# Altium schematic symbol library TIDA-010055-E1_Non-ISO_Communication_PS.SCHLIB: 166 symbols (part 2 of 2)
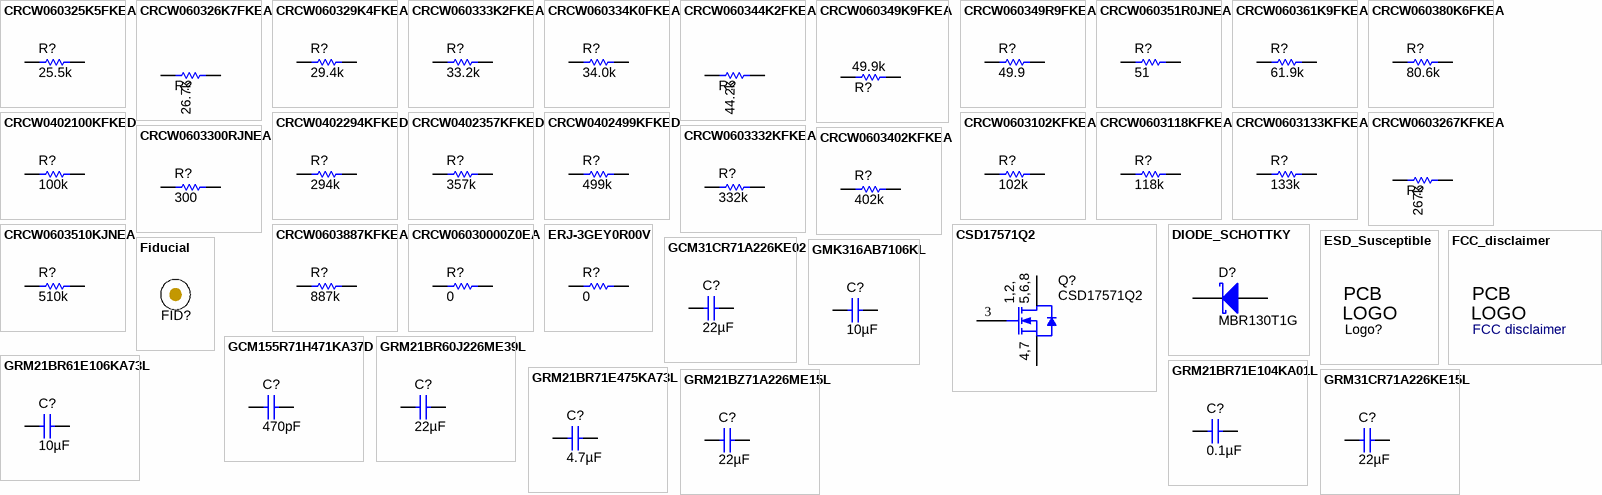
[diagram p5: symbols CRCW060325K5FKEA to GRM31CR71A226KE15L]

## CRCW0402499KFKED
designator R?  ValueDisplayed: 499k  (hidden comment: CRCW0402499KFKED)
RES, 499 k, 1%, 0.063 W, 0402; Manufacturer: Vishay-Dale; CompType: Resistor; Value: 499k; Res_ohm: 499000; Tolerance_%: 1; Power_W: 0.063; Value2: 0.063W; VDC_V: 50; TempCo: 100 ppm/C; EIA_Code: E96; U/M: EA; AEC Category: Q200
signal-integrity model Resistor
simulation model Resistor
footprint 0402
footprint 0402M
footprint 0402L
footprint 0402S
pins: 1, 2

## CRCW0603102KFKEA
designator R?  ValueDisplayed: 102k  (hidden comment: CRCW0603102KFKEA)
RES, 102 k, 1%, 0.1 W, 0603; Manufacturer: Vishay-Dale; CompType: Resistor; Value: 102k; Res_ohm: 102000; Tolerance_%: 1; Power_W: 0.1; Value2: 0.1W; VDC_V: 75; TempCo: 100 ppm/C; SizeArea_mm2: 1.28; SizeX_mm: 1.6; SizeY_mm: 0.8; EIA_Code: E96; U/M: EA; AEC Category: Q200; Green_Lifecycle: Active; Green_REACh: Passed
signal-integrity model Resistor
simulation model Resistor
footprint 0603
footprint 0603M
footprint 0603L
footprint 0603_HV
footprint 0603S
pins: 1, 2

## CRCW0603118KFKEA
designator R?  ValueDisplayed: 118k  (hidden comment: CRCW0603118KFKEA)
RES, 118 k, 1%, 0.1 W, 0603; Manufacturer: Vishay-Dale; CompType: Resistor; Value: 118k; Res_ohm: 118000; Tolerance_%: 1; Power_W: 0.1; Value2: 0.1W; VDC_V: 75; TempCo: 100 ppm/C; EIA_Code: E96; U/M: EA; AEC Category: Q200
signal-integrity model Resistor
simulation model Resistor
footprint 0603
footprint 0603M
footprint 0603L
footprint 0603_HV
footprint 0603S
pins: 1, 2

## CRCW0603133KFKEA
designator R?  ValueDisplayed: 133k  (hidden comment: CRCW0603133KFKEA)
RES, 133 k, 1%, 0.1 W, 0603; Manufacturer: Vishay-Dale; CompType: Resistor; Value: 133k; Res_ohm: 133000; Tolerance_%: 1; Power_W: 0.1; Value2: 0.1W; VDC_V: 75; TempCo: 100 ppm/C; SizeArea_mm2: 1.28; SizeX_mm: 1.6; SizeY_mm: 0.8; EIA_Code: E96; U/M: EA; AEC Category: Q200; Green_Lifecycle: Active; Green_REACh: Passed
signal-integrity model Resistor
simulation model Resistor
footprint 0603
footprint 0603M
footprint 0603L
footprint 0603_HV
footprint 0603S
pins: 1, 2

## CRCW0603267KFKEA
designator R?  ValueDisplayed: 267k  (hidden comment: CRCW0603267KFKEA)
RES, 267 k, 1%, 0.1 W, 0603; Manufacturer: Vishay-Dale; CompType: Resistor; Value: 267k; Res_ohm: 267000; Tolerance_%: 1; Power_W: 0.1; Value2: 0.1W; VDC_V: 75; TempCo: 100 ppm/C; SizeArea_mm2: 1.28; SizeX_mm: 1.6; SizeY_mm: 0.8; EIA_Code: E96; U/M: EA; AEC Category: Q200
signal-integrity model Resistor
simulation model Resistor
footprint 0603
footprint 0603M
footprint 0603L
footprint 0603_HV
footprint 0603S
pins: 1, 2

## CRCW0603300RJNEA
designator R?  ValueDisplayed: 300  (hidden comment: CRCW0603300RJNEA)
RES, 300, 5%, 0.1 W, 0603; Manufacturer: Vishay-Dale; CompType: Resistor; Value: 300; Value_Code: 300R; Tolerance_%: 5; Power_W: 0.1; Value2: 0.1W; VDC_V: 75; TempCo: 200 ppm/C; SizeArea_mm2: 1.28; SizeX_mm: 1.6; SizeY_mm: 0.8; SizeZ_mm: 1; EIA_Code: E24; U/M: EA; AEC Category: Q200
signal-integrity model Resistor
simulation model Resistor
footprint 0603
footprint 0603M
footprint 0603L
footprint 0603_HV
footprint 0603S
pins: 1, 2

## CRCW0603332KFKEA
designator R?  ValueDisplayed: 332k  (hidden comment: CRCW0603332KFKEA)
RES, 332 k, 1%, 0.1 W, 0603; Manufacturer: Vishay-Dale; CompType: Resistor; Value: 332k; Res_ohm: 332000; Tolerance_%: 1; Power_W: 0.1; Value2: 0.1W; VDC_V: 75; TempCo: 100 ppm/C; SizeArea_mm2: 1.28; SizeX_mm: 1.6; SizeY_mm: 0.8; EIA_Code: E96; U/M: EA; AEC Category: Q200; Green_Lifecycle: Active; Green_REACh: Passed
signal-integrity model Resistor
simulation model Resistor
footprint 0603
footprint 0603M
footprint 0603L
footprint 0603_HV
footprint 0603S
pins: 1, 2

## CRCW0603402KFKEA
designator R?  ValueDisplayed: 402k  (hidden comment: CRCW0603402KFKEA)
RES, 402 k, 1%, 0.1 W, 0603; Manufacturer: Vishay-Dale; CompType: Resistor; Value: 402k; Res_ohm: 402000; Tolerance_%: 1; Power_W: 0.1; Value2: 0.1W; VDC_V: 75; TempCo: 100 ppm/C; SizeArea_mm2: 1.28; SizeX_mm: 1.6; SizeY_mm: 0.8; EIA_Code: E96; U/M: EA; AEC Category: Q200; Green_Lifecycle: Active; Green_REACh: Passed
signal-integrity model Resistor
simulation model Resistor
footprint 0603
footprint 0603M
footprint 0603L
footprint 0603_HV
footprint 0603S
pins: 1, 2

## CRCW0603510KJNEA
designator R?  ValueDisplayed: 510k  (hidden comment: CRCW0603510KJNEA)
RES, 510 k, 5%, 0.1 W, 0603; Manufacturer: Vishay-Dale; CompType: Resistor; Value: 510k; Res_ohm: 510000; Tolerance_%: 5; Power_W: 0.1; Value2: 0.1W; VDC_V: 75; TempCo: 200 ppm/C; EIA_Code: E24; U/M: EA; AEC Category: Q200
signal-integrity model Resistor
simulation model Resistor
footprint 0603
footprint 0603M
footprint 0603L
footprint 0603_HV
footprint 0603S
pins: 1, 2

## CRCW0603887KFKEA
designator R?  ValueDisplayed: 887k  (hidden comment: CRCW0603887KFKEA)
RES, 887 k, 1%, 0.1 W, 0603; Manufacturer: Vishay-Dale; CompType: Resistor; Value: 887k; Res_ohm: 887000; Tolerance_%: 1; Power_W: 0.1; Value2: 0.1W; VDC_V: 75; TempCo: 100 ppm/C; SizeArea_mm2: 1.28; SizeX_mm: 1.6; SizeY_mm: 0.8; EIA_Code: E96; U/M: EA; AEC Category: Q200; Green_Lifecycle: Active; Green_REACh: Passed
signal-integrity model Resistor
simulation model Resistor
footprint 0603
footprint 0603M
footprint 0603L
footprint 0603_HV
footprint 0603S
pins: 1, 2

## CRCW06030000Z0EA
designator R?  ValueDisplayed: 0  (hidden comment: CRCW06030000Z0EA)
RES, 0, 5%, 0.1 W, 0603; Manufacturer: Vishay-Dale; CompType: Resistor; Value: 0; Value_Code: 0000; Tolerance_%: 5; Power_W: 0.1; Value2: 0.1W; VDC_V: 75; TempCo: 200 ppm/C; EIA_Code: E24; U/M: EA; AEC Category: Q200
signal-integrity model Resistor
simulation model Resistor
footprint 0603
footprint 0603M
footprint 0603L
footprint 0603_HV
footprint 0603S
pins: 1, 2

## CSD17571Q2
designator Q?
MOSFET, N-CH, 30 V, 22 A, DQK0006C (WSON-6); Manufacturer: Texas Instruments; Alternate Manufacturer: None; U/M: EA; ChType: N; Value: 30V; VdsMax_V: 30; Value1: 0.029 ohm; Rdson45_ohm: 0.029; Value2: 2.4 nC; QgTyp_nC: 2.4; Vgs_V: 20; IdsMax_A: 22; SizeAreaWB_mm2: 9; SizeArea_mm2: 4; SizeX_mm: 2; SizeZ_mm: 0.8; AEC Category: Q101
footprint DQK0006C
pins: 1 D, 2 D, 3 G, 4 S, 5 D, 6 D, 7 S, 8 D

## DIODE_SCHOTTKY
designator D?, comment MBR130T1G
Diode, Schottky, 30 V, 1 A, SOD-123; Manufacturer: ON Semiconductor; Io_A: 1A; Green_Lifecycle: Active; SizeAreaWB_mm2: 13.095; Vr_V: 30V; Green_REACh: Passed; TJmax_C: 125°C; U/M: EA; Value: 30V; SizeZ_mm: 1.35; SizeX_mm: 3.85; SizeY_mm: 1.7; Vf_V: 4.7dV; Value2: 0.47V; SizeArea_mm2: 6.545; AEC Category: Q101; RJC_CperW: 108
footprint SOD-123 (On Semi recommended land pattern)
pins: 1 K, 2 A

## ERJ-3GEY0R00V
designator R?  ValueDisplayed: 0  (hidden comment: ERJ-3GEY0R00V)
RES, 0, 5%, 0.1 W, 0603; Manufacturer: Panasonic; CompType: Resistor; Value: 0; Value_Code: 0000; Tolerance_%: 5; Power_W: 0.1; Value2: 0.1W; VDC_V: 50; TempCo: 600 ppm/C; SizeArea_mm2: 1.28; SizeX_mm: 1.6; SizeY_mm: 0.8; SizeZ_mm: 1; EIA_Code: E24; U/M: EA; AEC Category: Q200; Green_Lifecycle: Active; Green_REACh: Passed
signal-integrity model Resistor
simulation model Resistor
footprint 0603
footprint 0603M
footprint 0603L
footprint 0603_HV
footprint 0603S
pins: 1, 2

## ESD_Susceptible
designator Logo?, comment ESD Susceptible  (value not drawn)  (no BOM)
ESD Susceptible Symbol; SymbolCreator: a0412235
footprint ESD_Overlay_Large
footprint ESD_Overlay_Medium
footprint ESD_Overlay_Small

## FCC_disclaimer
designator Logo?, comment FCC disclaimer  (no BOM)
FCC_disclaimer; SymbolCreator: codlsc
footprint FCC_disclaimer
footprint FCC_disclaimer_stacked

## Fiducial
designator FID?  (value not drawn)
Fiducial mark.  There is nothing to buy or mount.; SymbolCreator: codlsc
footprint Fiducial10-30
footprint Fiducial10-20
footprint Fiducial15-30
footprint Fiducial20-40
footprint Fiducial6.4-20

## GCM31CR71A226KE02
designator C?  ValueDisplayed: 22µF  (hidden comment: GCM31CR71A226KE02)
CAP, CERM, 22 µF, 10 V, +/- 10%, X7R, AEC-Q200 Grade 1, 1206_190; Manufacturer: MuRata; Polarized: N; CompType: Capacitor; Value: 22uF; U/M: EA; Cap_F: 0.000022; Tolerance_%: 10; Value1: Unknown; Value2: 10V; TaMin_C: -55; TaMax_C: 125; Cap_Case: 1206; AEC Category: Q200; AEC Qualified: Y; AEC Grade: 1
signal-integrity model Cap
simulation model Cap
footprint 1206_190
footprint 1206_190M
footprint 1206_190L
pins: 1, 2

## GCM155R71H471KA37D
designator C?  ValueDisplayed: 470pF  (hidden comment: GCM155R71H471KA37D)
CAP, CERM, 470 pF, 50 V, +/- 10%, X7R, AEC-Q200 Grade 1, 0402; Manufacturer: MuRata; Polarized: N; CompType: Capacitor; Value: 470pF; U/M: EA; Cap_F: 0.00000000047; Tolerance_%: 10; Value1: Unknown; VDC_V: 50; Value2: 50V; TaMin_C: -55; TaMax_C: 125; Cap_Case: 0402; AEC Category: Q200; AEC Qualified: Y; AEC Grade: 1
signal-integrity model Cap
simulation model Cap
footprint 0402
footprint 0402M
footprint 0402L
footprint 0402S
pins: 1, 2

## GMK316AB7106KL
designator C?  ValueDisplayed: 10µF  (hidden comment: GMK316AB7106KL)
CAP, CERM, 10 µF, 35 V, +/- 10%, X7R, 1206; Manufacturer: Taiyo Yuden; Polarized: N; CompType: Capacitor; Value: 10uF; U/M: EA; Cap_F: 0.00001; Tolerance_%: 10; Value1: Unknown; VDC_V: 35; Value2: 35V; TaMin_C: -55; TaMax_C: 125; Cap_Case: 1206; AEC Category: Q200
signal-integrity model Cap
simulation model Cap
footprint 1206
footprint 1206M
footprint 1206L
pins: 1, 2

## GRM21BR60J226ME39L
designator C?  ValueDisplayed: 22µF  (hidden comment: GRM21BR60J226ME39L)
CAP, CERM, 22 µF, 6.3 V, +/- 20%, X5R, 0805; Manufacturer: MuRata; Polarized: N; CompType: Capacitor; Value: 22uF; U/M: EA; Cap_F: 0.000022; Tolerance_%: 20; ESR_ohm: 0.009; Value1: 0.009 ohm; VDC_V: 6.3; Value2: 6.3V; IRMS_A: 3.5; TaMin_C: -55; TaMax_C: 85; Cap_Case: 0805; AEC Category: Q200
signal-integrity model Cap
simulation model Cap
footprint 0805_HV
footprint 0805_HV1
footprint 0805
footprint 0805M
footprint 0805L
pins: 1, 2

## GRM21BR61E106KA73L
designator C?, comment ValueDisplayed: 10µF  (hidden comment: C2012X5R1E106K085AC)
CAP, CERM, 10 µF, 25 V, +/- 10%, X5R, 0805; Manufacturer: TDK Corporation; Polarized: N; CompType: Capacitor; Value: 10uF; U/M: EA; Cap_F: 0.00001; Tolerance_%: 10; Value1: Unknown; VDC_V: 25; Value2: 25V; TaMin_C: -55; TaMax_C: 85; Cap_Case: 0805; AEC Category: Q200
signal-integrity model Cap
simulation model Cap
footprint 0805_HV
footprint 0805_HV1
footprint 0805
footprint 0805M
footprint 0805L
pins: 1, 2

## GRM21BR71E104KA01L
designator C?  ValueDisplayed: 0.1µF  (hidden comment: GRM21BR71E104KA01L)
CAP, CERM, 0.1 µF, 25 V, +/- 10%, X7R, 0805; Manufacturer: MuRata; Polarized: N; CompType: Capacitor; Value: 0.1uF; U/M: EA; Cap_F: 0.0000001; Tolerance_%: 10; Value1: Unknown; VDC_V: 25; Value2: 25V; TaMin_C: -55; TaMax_C: 125; Cap_Case: 0805; AEC Category: Q200
signal-integrity model Cap
simulation model Cap
footprint 0805_HV
footprint 0805_HV1
footprint 0805
footprint 0805M
footprint 0805L
pins: 1, 2

## GRM21BR71E475KA73L
designator C?  ValueDisplayed: 4.7µF  (hidden comment: GRM21BR71E475KA73L)
CAP, CERM, 4.7 µF, 25 V,+/- 10%, X7R, 0805; Manufacturer: MuRata; Polarized: N; CompType: Capacitor; Value: 4.7uF; U/M: EA; Cap_F: 0.0000047; Tolerance_%: 10; VDC_V: 25; Value2: 25V; TaMin_C: -55; TaMax_C: 125; Cap_Case: 0805; SizeArea_mm2: 2.5; SizeAreaWB_mm2: 6.75; SizeX_mm: 2; SizeY_mm: 1.25; SizeZ_mm: 1.45; AEC Category: Q200
signal-integrity model Cap
simulation model Cap
footprint 0805_HV
footprint 0805_HV1
footprint 0805
footprint 0805M
footprint 0805L
pins: 1, 2

## GRM21BZ71A226ME15L
designator C?  ValueDisplayed: 22µF  (hidden comment: GRM21BZ71A226ME15L)
CAP, CERM, 22 µF, 10 V, +/- 20%, X7R, 0805; Manufacturer: MuRata; Polarized: N; CompType: Capacitor; Value: 22uF; U/M: EA; Cap_F: 0.000022; Tolerance_%: 20; Value1: Unknown; VDC_V: 10; Value2: 10V; TaMin_C: -55; TaMax_C: 125; Cap_Case: 0805; AEC Category: Q200
signal-integrity model Cap
simulation model Cap
footprint 0805_HV
footprint 0805_HV1
footprint 0805
footprint 0805M
footprint 0805L
pins: 1, 2

## GRM31CR71A226KE15L
designator C?  ValueDisplayed: 22µF  (hidden comment: GRM31CR71A226KE15L)
CAP, CERM, 22 µF, 10 V, +/- 10%, X7R, 1206; Manufacturer: MuRata; Polarized: N; CompType: Capacitor; Value: 22uF; U/M: EA; Cap_F: 0.000022; Tolerance_%: 10; Value1: Unknown; Value2: 10V; TaMin_C: -55; TaMax_C: 125; Cap_Case: 1206; AEC Category: Q200
signal-integrity model Cap
simulation model Cap
footprint 1206 (1206 from SM-752 data)
footprint 1206M
footprint 1206L
pins: 1, 2

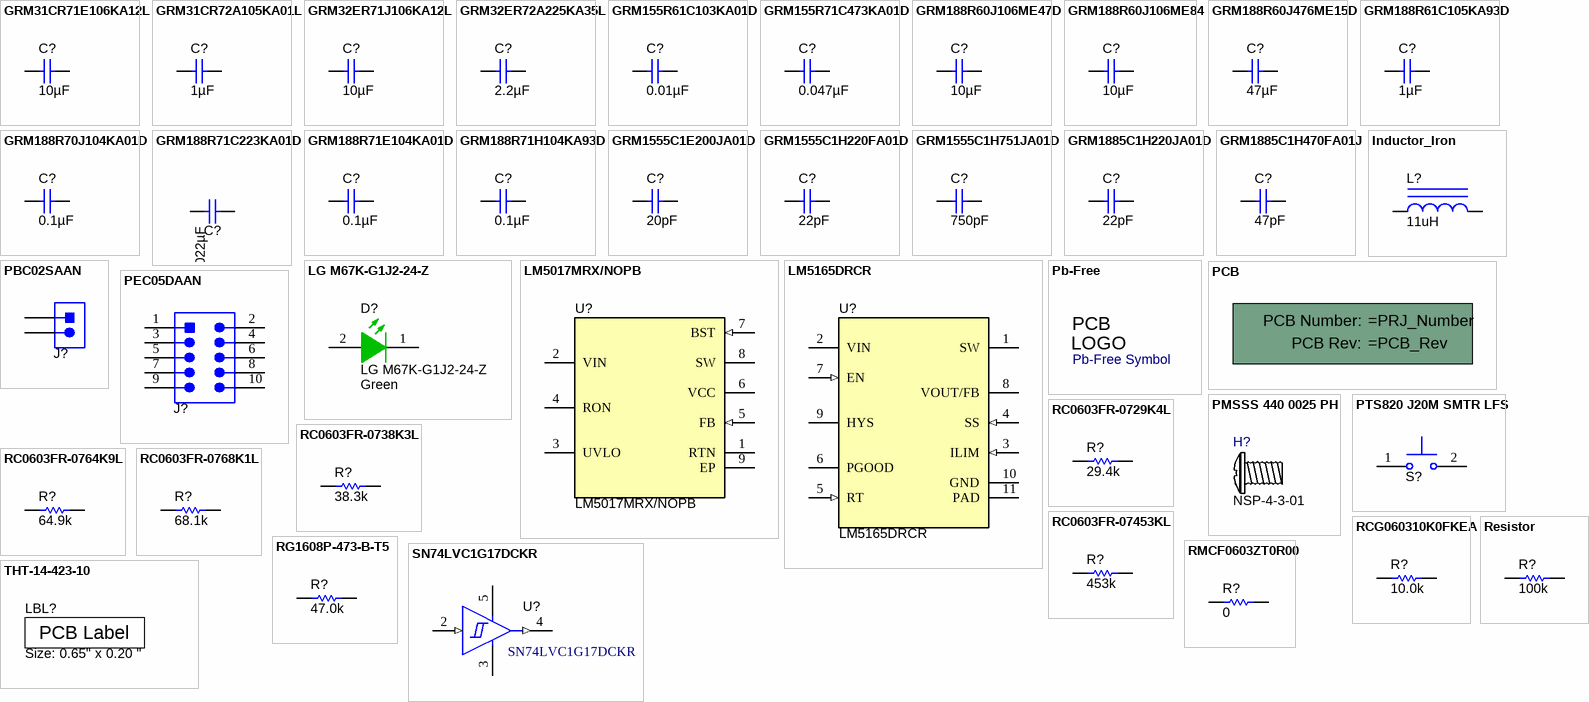
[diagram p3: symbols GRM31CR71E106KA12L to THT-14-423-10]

## GRM31CR71E106KA12L
designator C?  ValueDisplayed: 10µF  (hidden comment: GRM31CR71E106KA12L)
CAP, CERM, 10 µF, 25 V, +/- 10%, X7R, 1206; Manufacturer: MuRata; Polarized: N; CompType: Capacitor; Value: 10uF; U/M: EA; Cap_F: 0.00001; Tolerance_%: 10; Value1: Unknown; VDC_V: 25; Value2: 25V; TaMin_C: -55; TaMax_C: 125; Cap_Case: 2220; AEC Category: Q200
signal-integrity model Cap
simulation model Cap
footprint 1206 (1206 from SM-752 data)
footprint 1206M
footprint 1206L
pins: 1, 2

## GRM31CR72A105KA01L
designator C?  ValueDisplayed: 1µF  (hidden comment: GRM31CR72A105KA01L)
CAP, CERM, 1 µF, 100 V, +/- 10%, X7R, 1206; Manufacturer: MuRata; Polarized: N; CompType: Capacitor; Value: 1uF; U/M: EA; Cap_F: 0.000001; Tolerance_%: 10; Value1: Unknown; VDC_V: 100; Value2: 100V; TaMin_C: -55; TaMax_C: 125; Cap_Case: 2220; AEC Category: Q200
signal-integrity model Cap
simulation model Cap
footprint 1206 (1206 from SM-752 data)
footprint 1206M
footprint 1206L
pins: 1, 2

## GRM32ER71J106KA12L
designator C?  ValueDisplayed: 10µF  (hidden comment: GRM32ER71J106KA12L)
CAP, CERM, 10 µF, 63 V, +/- 10%, X7R, 1210; Manufacturer: MuRata; Polarized: N; CompType: Capacitor; Value: 10uF; U/M: EA; Cap_F: 0.00001; Tolerance_%: 10; Value1: Unknown; VDC_V: 63; Value2: 63V; TaMin_C: -55; TaMax_C: 125; Cap_Case: 1210; SizeArea_mm2: 8; SizeAreaWB_mm2: 14.7; SizeX_mm: 3.2; SizeY_mm: 2.5; SizeZ_mm: 2.7; AEC Category: Q200
signal-integrity model Cap
simulation model Cap
footprint 1210_270
footprint 1210_270M
footprint 1210_270L
pins: 1, 2

## GRM32ER72A225KA35L
designator C?  ValueDisplayed: 2.2µF  (hidden comment: GRM32ER72A225KA35L)
CAP, CERM, 2.2 µF, 100 V, +/- 10%, X7R, 1210; Manufacturer: MuRata; Polarized: N; CompType: Capacitor; Value: 2.2uF; U/M: EA; Cap_F: 0.0000022; Tolerance_%: 10; ESR_ohm: 0.007; Value1: 0.007 ohm; VDC_V: 100; Value2: 100V; IRMS_A: 4.4; TaMin_C: -55; TaMax_C: 125; Cap_Case: 1210; SizeArea_mm2: 8; SizeAreaWB_mm2: 14.7; SizeX_mm: 3.2; SizeY_mm: 2.5; SizeZ_mm: 2.7; AEC Category: Q200
signal-integrity model Cap
simulation model Cap
footprint 1210_270
footprint 1210_270M
footprint 1210_270L
pins: 1, 2

## GRM155R61C103KA01D
designator C?  ValueDisplayed: 0.01µF  (hidden comment: GRM155R61C103KA01D)
CAP, CERM, 0.01 µF, 16 V, +/- 10%, X5R, 0402; Manufacturer: MuRata; Polarized: N; CompType: Capacitor; Value: 0.01uF; U/M: EA; Cap_F: 0.00000001; Tolerance_%: 10; Value1: Unknown; VDC_V: 16; Value2: 16V; TaMin_C: -55; TaMax_C: 85; Cap_Case: 0402; SizeArea_mm2: 0.5; SizeAreaWB_mm2: 3; SizeX_mm: 1; SizeZ_mm: 0.6; AEC Category: Q200
signal-integrity model Cap
simulation model Cap
footprint 0402
footprint 0402M
footprint 0402L
footprint 0402S
pins: 1, 2

## GRM155R71C473KA01D
designator C?  ValueDisplayed: 0.047µF  (hidden comment: GRM155R71C473KA01D)
CAP, CERM, 0.047 µF, 16 V, +/- 10%, X7R, 0402; Manufacturer: MuRata; Polarized: N; CompType: Capacitor; Value: 0.047uF; U/M: EA; Cap_F: 0.000000047; Tolerance_%: 10; Value1: Unknown; VDC_V: 16; Value2: 16V; TaMin_C: -55; TaMax_C: 125; Cap_Case: 0402; AEC Category: Q200
signal-integrity model Cap
simulation model Cap
footprint 0402
footprint 0402M
footprint 0402L
footprint 0402S
pins: 1, 2

## GRM188R60J106ME47D
designator C?  ValueDisplayed: 10µF  (hidden comment: GRM188R60J106ME47D)
CAP, CERM, 10 µF, 6.3 V, +/- 20%, X5R, 0603; Manufacturer: MuRata; Polarized: N; CompType: Capacitor; Value: 10uF; U/M: EA; Cap_F: 0.00001; Tolerance_%: 20; ESR_ohm: 0.009; Value1: 0.009 ohm; VDC_V: 6.3; Value2: 6.3V; IRMS_A: 2.74; TaMin_C: -55; TaMax_C: 125; Cap_Case: 0603; SizeArea_mm2: 1.28; SizeAreaWB_mm2: 4.68; SizeX_mm: 1.6; SizeY_mm: 0.8; SizeZ_mm: 1; AEC Category: Q200
signal-integrity model Cap
simulation model Cap
footprint 0603
footprint 0603M
footprint 0603L
footprint 0603_HV
footprint 0603S
pins: 1, 2

## GRM188R60J106ME84
designator C?  ValueDisplayed: 10µF  (hidden comment: GRM188R60J106ME84)
CAP, CERM, 10 µF, 6.3 V, +/- 20%, X5R, 0603; Manufacturer: MuRata; Polarized: N; CompType: Capacitor; Value: 10uF; U/M: EA; Cap_F: 0.00001; Tolerance_%: 20; Value1: Unknown; VDC_V: 6.3; Value2: 6.3V; TaMin_C: -55; TaMax_C: 85; Cap_Case: 0603; AEC Category: Q200
signal-integrity model Cap
simulation model Cap
footprint 0603
footprint 0603M
footprint 0603L
footprint 0603_HV
footprint 0603S
pins: 1, 2

## GRM188R60J476ME15D
designator C?  ValueDisplayed: 47µF  (hidden comment: GRM188R60J476ME15D)
CAP, CERM, 47 µF, 6.3 V,+/- 20%, X5R, 0603; Manufacturer: MuRata; Polarized: N; CompType: Capacitor; Value: 47uF; U/M: EA; Cap_F: 0.000047; Tolerance_%: 20; VDC_V: 6.3; Value2: 6.3V; TaMin_C: -55; TaMax_C: 85; Cap_Case: 0603; SizeArea_mm2: 1.28; SizeAreaWB_mm2: 4.68; SizeX_mm: 1.6; SizeY_mm: 0.8; SizeZ_mm: 1; AEC Category: Q200; Green_Lifecycle: Active; Green_REACh: Passed
signal-integrity model Cap
simulation model Cap
footprint 0603
footprint 0603M
footprint 0603L
footprint 0603_HV
footprint 0603S
pins: 1, 2

## GRM188R61C105KA93D
designator C?  ValueDisplayed: 1µF  (hidden comment: GRM188R61C105KA93D)
CAP, CERM, 1 µF, 16 V, +/- 10%, X5R, 0603; Manufacturer: MuRata; Polarized: N; CompType: Capacitor; Value: 1uF; U/M: EA; Cap_F: 0.000001; Tolerance_%: 10; Value1: Unknown; VDC_V: 16; Value2: 16V; TaMin_C: -55; TaMax_C: 85; Cap_Case: 0603; SizeArea_mm2: 1.28; SizeAreaWB_mm2: 4.68; SizeX_mm: 1.6; SizeY_mm: 0.8; SizeZ_mm: 1; AEC Category: Q200
signal-integrity model Cap
simulation model Cap
footprint 0603
footprint 0603M
footprint 0603L
footprint 0603_HV
footprint 0603S
pins: 1, 2

## GRM188R70J104KA01D
designator C?  ValueDisplayed: 0.1µF  (hidden comment: GRM188R70J104KA01D)
CAP, CERM, 0.1 µF, 6.3 V, +/- 10%, X7R, 0603; Manufacturer: MuRata; Polarized: N; CompType: Capacitor; Value: 0.1uF; U/M: EA; Cap_F: 0.0000001; Tolerance_%: 10; Value1: Unknown; VDC_V: 6.3; Value2: 6.3V; TaMin_C: -55; TaMax_C: 125; Cap_Case: 0603; AEC Category: Q200
signal-integrity model Cap
simulation model Cap
footprint 0603
footprint 0603M
footprint 0603L
footprint 0603_HV
footprint 0603S
pins: 1, 2

## GRM188R71C223KA01D
designator C?  ValueDisplayed: 0.022µF  (hidden comment: GRM188R71C223KA01D)
CAP, CERM, 0.022 µF, 16 V,+/- 10%, X7R, 0603; Manufacturer: MuRata; Polarized: N; CompType: Capacitor; Value: 0.022uF; U/M: EA; Cap_F: 0.000000022; Tolerance_%: 10; VDC_V: 16; Value2: 16V; TaMin_C: -55; TaMax_C: 125; Cap_Case: 0603; SizeArea_mm2: 1.28; SizeAreaWB_mm2: 4.68; SizeX_mm: 1.6; SizeY_mm: 0.8; SizeZ_mm: 1; AEC Category: Q200; Green_Lifecycle: Active; Green_REACh: Passed
signal-integrity model Cap
simulation model Cap
footprint 0603
footprint 0603M
footprint 0603L
footprint 0603_HV
footprint 0603S
pins: 1, 2

## GRM188R71E104KA01D
designator C?  ValueDisplayed: 0.1µF  (hidden comment: GRM188R71E104KA01D)
CAP, CERM, 0.1 µF, 25 V, +/- 10%, X7R, 0603; Manufacturer: MuRata; Polarized: N; CompType: Capacitor; Value: 0.1uF; U/M: EA; Cap_F: 0.0000001; Tolerance_%: 10; Value1: Unknown; VDC_V: 25; Value2: 25V; TaMin_C: -55; TaMax_C: 125; Cap_Case: 0603; AEC Category: Q200
signal-integrity model Cap
simulation model Cap
footprint 0603
footprint 0603M
footprint 0603L
footprint 0603_HV
footprint 0603S
pins: 1, 2

## GRM188R71H104KA93D
designator C?, comment ValueDisplayed: 0.1µF  (hidden comment: C0603X124K5RAC7867)
CAP, CERM, 0.12µF ±10% 50V Ceramic Capacitor X7R 0603; Manufacturer: KEMET; Polarized: N; Value: 0.1uF; U/M: EA; Cap_F: 0.0000001; Tolerance_%: 10; VDC_V: 50; TaMin_C: -55; TaMax_C: 125; Cap_Case: 0603; SizeArea_mm2: 1.28; SizeAreaWB_mm2: 4.68; SizeX_mm: 1.6; SizeY_mm: 0.8; SizeZ_mm: 1; AEC Category: Q200; Green_Lifecycle: Active; Green_REACh: Passed
signal-integrity model Cap
simulation model Cap
footprint 0603
footprint 0603M
footprint 0603L
footprint 0603_HV
footprint 0603S
pins: 1, 2

## GRM1555C1E200JA01D
designator C?, comment ValueDisplayed: 20pF  (hidden comment: CFF)
CAP, CERM, 20 pF, 25 V,+/- 5%, C0G/NP0, 0402; PartNumber: GRM1555C1E200JA01D; Manufacturer: MuRata; Polarized: N; CompType: Capacitor; Value: 20pF; U/M: EA; Cap_F: 0.00000000002; Tolerance_%: 5; VDC_V: 25; Value2: 25V; TaMin_C: -55; TaMax_C: 125; Cap_Case: 0402; SizeArea_mm2: 0.5; SizeAreaWB_mm2: 3; SizeX_mm: 1; SizeZ_mm: 0.6; AEC Category: Q200
signal-integrity model Cap
simulation model Cap
footprint 0402
footprint 0402M
footprint 0402L
footprint 0402S
pins: 1, 2

## GRM1555C1H220FA01D
designator C?  ValueDisplayed: 22pF  (hidden comment: GRM1555C1H220FA01D)
CAP, CERM, 22 pF, 50 V, +/- 1%, C0G/NP0, 0402; Manufacturer: MuRata; Polarized: N; CompType: Capacitor; Value: 22pF; U/M: EA; Cap_F: 0.000000000022; Tolerance_%: 1; Value1: Unknown; VDC_V: 50; Value2: 50V; TaMin_C: -55; TaMax_C: 125; Cap_Case: 0402; AEC Category: Q200
signal-integrity model Cap
simulation model Cap
footprint 0402
footprint 0402M
footprint 0402L
footprint 0402S
pins: 1, 2

## GRM1555C1H751JA01D
designator C?  ValueDisplayed: 750pF  (hidden comment: GRM1555C1H751JA01D)
CAP, CERM, 750 pF, 50 V, +/- 5%, C0G/NP0, 0402; Manufacturer: MuRata; Polarized: N; CompType: Capacitor; Value: 750pF; U/M: EA; Cap_F: 0.00000000075; Tolerance_%: 5; Value1: Unknown; VDC_V: 50; Value2: 50V; TaMin_C: -55; TaMax_C: 125; Cap_Case: 0402; SizeArea_mm2: 0.5; SizeAreaWB_mm2: 3; SizeX_mm: 1; SizeZ_mm: 0.6; AEC Category: Q200
signal-integrity model Cap
simulation model Cap
footprint 0402
footprint 0402M
footprint 0402L
footprint 0402S
pins: 1, 2

## GRM1885C1H220JA01D
designator C?  ValueDisplayed: 22pF  (hidden comment: GRM1885C1H220JA01D)
CAP, CERM, 22 pF, 50 V, +/- 5%, C0G/NP0, 0603; Manufacturer: MuRata; Polarized: N; CompType: Capacitor; Value: 22pF; U/M: EA; Cap_F: 0.000000000022; Tolerance_%: 5; Value1: Unknown; VDC_V: 50; Value2: 50V; TaMin_C: -55; TaMax_C: 125; Cap_Case: 0603; AEC Category: Q200
signal-integrity model Cap
simulation model Cap
footprint 0603
footprint 0603M
footprint 0603L
footprint 0603_HV
footprint 0603S
pins: 1, 2

## GRM1885C1H470FA01J
designator C?  ValueDisplayed: 47pF  (hidden comment: GRM1885C1H470FA01J)
CAP, CERM, 47 pF, 50 V,+/- 1%, C0G/NP0, 0603; Manufacturer: MuRata; Polarized: N; CompType: Capacitor; Value: 47pF; U/M: EA; Cap_F: 0.000000000047; Tolerance_%: 1; VDC_V: 50; Value2: 50V; TaMin_C: -55; TaMax_C: 125; Cap_Case: 0603; SizeArea_mm2: 1.28; SizeAreaWB_mm2: 4.68; SizeX_mm: 1.6; SizeY_mm: 0.8; AEC Category: Q200; Green_Lifecycle: Not Set; Green_REACh: Incomplete
signal-integrity model Cap
simulation model Cap
footprint 0603
footprint 0603M
footprint 0603L
footprint 0603_HV
footprint 0603S
pins: 1, 2

## Inductor_Iron
designator L?, comment ValueDisplayed: 11uH  (hidden comment: 7447798111)
Inductor, Shielded, Metal Composite, 11 uH, 5.3 A, 0.014 ohm, SMD; Manufacturer: Wurth Elektronik; Isat: 5.3A @ 10% inductance drop; Irms: 6.9A @ 40C rise; Green_Lifecycle: Active; SizeAreaWB_mm2: 148.84; DCR_ohm: 0.014; Green_REACh: Passed; Value: 11uH; Imax_A: 5.3A; SizeZ_mm: 6.4; SizeX_mm: 10.2; SizeArea_mm2: 104.04; Ind_H: 11µH; AEC Category: Q200
footprint WE-PDF_1064 (WERTH)
pins: 1, 2

## LG M67K-G1J2-24-Z
designator D?  value Green
LED, Green, SMD; Manufacturer: OSRAM; SymbolCreator: Altium; Type: AlInGaP; Vf_V: 1.8; Value2: 1.8V; Io_A: 0.002; Vr_V: 12; Tjmax_C: 125; Value1: W; Angle: 120; U/M: EA
footprint LG_M67K_Green
pins: 1 K, 2 A

## LM5017MRX/NOPB
designator U?
100V, 600mA Constant On-Time Synchronous Buck Regulator, DDA0008B; Alternate PartNumber: LM5017MR/NOPB; Manufacturer: Texas Instruments; SymbolCreator: a0412235; SizeArea_mm2: 31; SizeAreaWB_mm2: 57.4; SizeX_mm: 5; SizeY_mm: 6.2; SizeZ_mm: 1.7; CompType: IC; U/M: EA
footprint DDA0008B_N
footprint DDA0008B_M
footprint DDA0008B_L
pins: 1 RTN (power), 2 VIN (power), 3 UVLO, 4 RON, 5 FB (in), 6 VCC (power), 7 BST (in), 8 SW (power), 9 EP (power)

## LM5165DRCR
designator U?
3.0-V to 65-V Input, 150-mA Output, Ultra-Low Quiescent (ULQ) Synchronous Step-Down Voltage Regulator, DRC0010J; Alternate PartNumber: LM5165DRCT; Manufacturer: Texas Instruments; SymbolCreator: Altium; CompType: IC; U/M: EA
footprint DRC0010J (SON, 10-Leads, Body 3x3mm, Pitch 0.5mm, Thermal Pad 2.4x1.65mm, TI Recommended)
pins: 1 SW (power), 2 VIN (power), 3 ILIM (in), 4 SS (in), 5 RT (in), 6 PGOOD (oc), 7 EN (in), 8 VOUT/FB, 9 HYS, 10 GND (power), 11 PAD (power)
1 alternate drawing of the same symbol

## Pb-Free
designator Logo?, comment Pb-Free Symbol  (no BOM)
SymbolCreator: a0412235
footprint Pb-Free_Overlay_Medium
footprint Pb-Free_Overlay_Small

## PBC02SAAN
designator J?  (value not drawn)
Header, 100mil, 2x1, Gold, TH; Manufacturer: Sullins Connector Solutions; SymbolCreator: a0412235; Pitch_mm: 2.54; Gender: Male; Shrouded: N; Row_Count: 1; Current_A: 3; Voltage_V: 1800; Cert_UL: Y
footprint Sullins_PBC02SAAN
pins: 1, 2
1 alternate drawing of the same symbol

## PCB
designator !PCB?, comment Printed Circuit Board  (value not drawn)  (mechanical)
Manufacturer: Any; SymbolCreator: a0412235; CompType: PCB
1 alternate drawing of the same symbol

## PEC05DAAN
designator J?  (value not drawn)
Header, 100mil, 5x2, Tin, TH; Manufacturer: Sullins Connector Solutions; SymbolCreator: a0412235; Pitch_mm: 2.54; Gender: Male; Shrouded: N; Row_Count: 2; Current_A: 3; Voltage_V: 1800; Cert_UL: Y
footprint CONN_PEC05DAAN
pins: 1, 2, 3, 4, 5, 6, 7, 8, 9, 10

## PMSSS 440 0025 PH
designator H?, comment NSP-4-3-01
MACHINE SCREW PAN PHILLIPS 4-40; Manufacturer: Essentra Components; CompType: Standoff; SymbolCreator: a0412235
footprint B_F_PMSSS4400025PH

## PTS820 J20M SMTR LFS
designator S?  (value not drawn)
Switch, SPST-NO,  Off-Mom, 0.05A, 12VDC, SMD; Manufacturer: C&K Components; SymbolCreator: a0412235; VDC_V: 12; PositionCount: 1; CurrentRating_mA: 50
footprint SW_PTS820
pins: 1, 2

## RC0603FR-0729K4L
designator R?  ValueDisplayed: 29.4k  (hidden comment: RC0603FR-0729K4L)
RES, 29.4 k, 1%, 0.1 W, 0603; Manufacturer: Yageo America; CompType: Resistor; Value: 29.4k; Res_ohm: 29400; Value_Code: 29k4; Tolerance_%: 1; Power_W: 0.1; Value2: 0.1W; VDC_V: 150; TempCo: 200 ppm/C; SizeArea_mm2: 1.28; SizeX_mm: 1.6; SizeY_mm: 0.8; EIA_Code: E96; U/M: EA; AEC Category: Q200; Green_Lifecycle: Active; Green_REACh: Passed
signal-integrity model Resistor
simulation model Resistor
footprint 0603
footprint 0603M
footprint 0603L
footprint 0603_HV
footprint 0603S
pins: 1, 2

## RC0603FR-0738K3L
designator R?  ValueDisplayed: 38.3k  (hidden comment: RC0603FR-0738K3L)
RES, 38.3 k, 1%, 0.1 W, 0603; Manufacturer: Yageo America; CompType: Resistor; Value: 38.3k; Res_ohm: 38300; Value_Code: 38k3; Tolerance_%: 1; Power_W: 0.1; Value2: 0.1W; VDC_V: 150; TempCo: 200 ppm/C; EIA_Code: E96; U/M: EA; AEC Category: Q200; SizeArea_mm2: 1.28; SizeX_mm: 1.6; SizeY_mm: 0.8; Green_Lifecycle: Active; Green_REACh: Passed
signal-integrity model Resistor
simulation model Resistor
footprint 0603
footprint 0603M
footprint 0603L
footprint 0603_HV
footprint 0603S
pins: 1, 2

## RC0603FR-0764K9L
designator R?  ValueDisplayed: 64.9k  (hidden comment: RC0603FR-0764K9L)
RES, 64.9 k, 1%, 0.1 W, 0603; Manufacturer: Yageo America; CompType: Resistor; Value: 64.9k; Res_ohm: 64900; Value_Code: 64k9; Tolerance_%: 1; Power_W: 0.1; Value2: 0.1W; VDC_V: 150; TempCo: 200 ppm/C; EIA_Code: E96; U/M: EA; AEC Category: Q200; SizeArea_mm2: 1.28; SizeX_mm: 1.6; SizeY_mm: 0.8
signal-integrity model Resistor
simulation model Resistor
footprint 0603
footprint 0603M
footprint 0603L
footprint 0603_HV
footprint 0603S
pins: 1, 2

## RC0603FR-0768K1L
designator R?  ValueDisplayed: 68.1k  (hidden comment: RC0603FR-0768K1L)
RES, 68.1 k, 1%, 0.1 W, 0603; Manufacturer: Yageo America; CompType: Resistor; Value: 68.1k; Res_ohm: 68100; Value_Code: 68k1; Tolerance_%: 1; Power_W: 0.1; Value2: 0.1W; VDC_V: 150; TempCo: 200 ppm/C; SizeArea_mm2: 1.28; SizeX_mm: 1.6; SizeY_mm: 0.8; EIA_Code: E96; U/M: EA; AEC Category: Q200
signal-integrity model Resistor
simulation model Resistor
footprint 0603
footprint 0603M
footprint 0603L
footprint 0603_HV
footprint 0603S
pins: 1, 2

## RC0603FR-07453KL
designator R?  ValueDisplayed: 453k  (hidden comment: RC0603FR-07453KL)
RES, 453 k, 1%, 0.1 W, 0603; Manufacturer: Yageo America; CompType: Resistor; Value: 453k; Res_ohm: 453000; Tolerance_%: 1; Power_W: 0.1; Value2: 0.1W; VDC_V: 150; TempCo: 200 ppm/C; SizeArea_mm2: 1.28; SizeX_mm: 1.6; SizeY_mm: 0.8; EIA_Code: E96; U/M: EA; AEC Category: Q200
signal-integrity model Resistor
simulation model Resistor
footprint 0603
footprint 0603M
footprint 0603L
footprint 0603_HV
footprint 0603S
pins: 1, 2

## RCG060310K0FKEA
designator R?  ValueDisplayed: 10.0k  (hidden comment: RCG060310K0FKEA)
RES, 10.0 k, 1%, 0.1 W, 0603; Manufacturer: Vishay Draloric; CompType: Resistor; Value: 10.0k; Res_ohm: 10000; Value_Code: 10k0; Tolerance_%: 1; Power_W: 0.1; Value2: 0.1W; VDC_V: 75; TempCo: 100 ppm/C; EIA_Code: E96; U/M: EA; AEC Category: Q200; AEC Qualified: N; SizeArea_mm2: 1.28; SizeX_mm: 1.6; SizeY_mm: 0.8
signal-integrity model Resistor
simulation model Resistor
footprint 0603
footprint 0603M
footprint 0603L
footprint 0603_HV
footprint 0603S
pins: 1, 2

## Resistor
designator R?, comment ValueDisplayed: 100k  (hidden comment: ERA-3AEB104V)
RES, 100 k, 0.1%, 0.1 W, AEC-Q200 Grade 0, 0603; Manufacturer: Panasonic; Power_W: 100mW; TempCo: 25 ppm/C; U/M: EA; Value: 100k; EIA_Code: E192; SizeX_mm: 1.6; SizeY_mm: 0.8; SizeZ_mm: 1; Value2: 0.1W; SizeArea_mm2: 1.28; CompType: Resistor; AEC Qualified: Y; VDC_V: 75V; AEC Grade: 0; AEC Category: Q200
footprint 0603 (0603 from SM-752 data)
footprint 0603_HV (Ernesto recommended land pattern.  26 mil between pads.)
footprint 0603L (0603 from SM-752 data)
footprint 0603S
footprint 0603M (0603 from SM-752 data)
pins: 1, 2

## RG1608P-473-B-T5
designator R?  ValueDisplayed: 47.0k  (hidden comment: RG1608P-473-B-T5)
RES, 47.0 k, 0.1%, 0.1 W, 0603; Manufacturer: Susumu Co Ltd; CompType: Resistor; Value: 47.0k; Res_ohm: 47000; Value_Code: 47k0; Tolerance_%: 0.1; Value2: 0.1W; VDC_V: 75; TempCo: 25 ppm/C; SizeArea_mm2: 1.28; SizeX_mm: 1.6; SizeY_mm: 0.8; SizeZ_mm: 1; EIA_Code: E192; U/M: EA; AEC Category: Q200
signal-integrity model Resistor
simulation model Resistor
footprint 0603
footprint 0603M
footprint 0603L
footprint 0603_HV
footprint 0603S
pins: 1, 2

## RMCF0603ZT0R00
designator R?  ValueDisplayed: 0  (hidden comment: RMCF0603ZT0R00)
RES, 0, 1%, 0.1 W, AEC-Q200 Grade 0, 0603; Manufacturer: Stackpole Electronics Inc; CompType: Resistor; Value: 0; Tolerance_%: 1; Power_W: 0.1; Value2: 0.1W; TempCo: ppm/C; SizeArea_mm2: 1.28; SizeX_mm: 1.6; SizeY_mm: 0.8; U/M: EA; AEC Category: Q200; AEC Qualified: Y
signal-integrity model Resistor
simulation model Resistor
footprint 0603
footprint 0603M
footprint 0603L
footprint 0603_HV
footprint 0603S
pins: 1, 2

## SN74LVC1G17DCKR
designator U?
SINGLE SCHMITT-TRIGGER BUFFER, DCK0005A (SOT-SC70-5); Alternate PartNumber: SN74LVC1G17DCKT; Manufacturer: Texas Instruments; SymbolCreator: a0799628; SizeArea_mm2: 4.2; SizeAreaWB_mm2: 9.3; SizeX_mm: 2.1; SizeY_mm: 2; SizeZ_mm: 1.1; CompType: IC; U/M: EA
footprint DCK0005A_N
footprint DCK0005A_M
footprint DCK0005A_L
pins: 2 A (in), 3 GND (power), 4 Y (out), 5 VCC (power)

## THT-14-423-10
designator LBL?, comment Size: 0.65" x 0.20 "
Thermal Transfer Printable Labels, 0.650" W x 0.200" H - 10,000 per roll; Manufacturer: Brady; PartNumber: THT-14-423-10; SymbolCreator: a0412235; CompType: Label
footprint Label_650x200

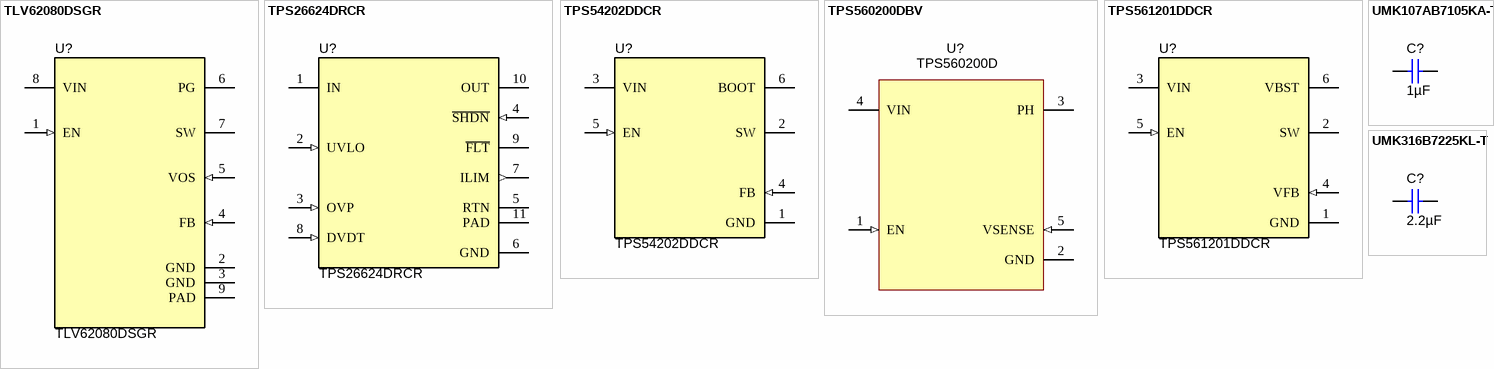
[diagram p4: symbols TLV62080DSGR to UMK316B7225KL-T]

## TLV62080DSGR
designator U?
1.2A High Efficient Step Down Converter in 2x2mm SON Package, DSG0008A (WSON-8); Alternate PartNumber: TLV62080DSGT; Manufacturer: Texas Instruments; SymbolCreator: a0411947; SizeArea_mm2: 4; SizeAreaWB_mm2: 9; SizeX_mm: 2; SizeZ_mm: 0.8; CompType: IC; U/M: EA
footprint DSG0008A
footprint DSG0008A_NV
pins: 1 EN (in), 2 GND (power), 3 GND (power), 4 FB (in), 5 VOS (in), 6 PG (oc), 7 SW (power), 8 VIN (power), 9 PAD (power)
1 alternate drawing of the same symbol

## TPS26624DRCR
designator U?
7V - 57V, 800mA Industrial eFuse with Integrated Reverse Polarity Protection, DRC0010J (VSON-10); Alternate PartNumber: TPS26625DRCR; Manufacturer: Texas Instruments; SymbolCreator: a0411947; SizeArea_mm2: 9; SizeAreaWB_mm2: 16; SizeX_mm: 3; SizeZ_mm: 1; CompType: IC; U/M: EA
footprint DRC0010J
footprint DRC0010J_NV
pins: 1 IN (power), 2 UVLO (in), 3 OVP (in), 4 ~{SHDN} (in), 5 RTN, 6 GND (power), 7 ILIM (out), 8 DVDT (in), 9 ~{FLT} (oc), 10 OUT (power), 11 PAD (power)
1 alternate drawing of the same symbol

## TPS54202DDCR
designator U?
4.5-V TO 28-V INPUT, 2-A OUTPUT, EMI FRIENDLY SYNCHRONUOUS STEP-DOWN CONVERTOR, DDC0006A; Alternate PartNumber: TPS54202DDCT; Manufacturer: Texas Instruments; SymbolCreator: a0411947; CompType: IC; U/M: EA
footprint DDC0006A_N
footprint DDC0006A_M
footprint DDC0006A_L
pins: 1 GND (power), 2 SW (power), 3 VIN (power), 4 FB (in), 5 EN (in), 6 BOOT (power)

## TPS560200DBV
designator U?, comment value TPS560200D  (hidden comment: TPS560200DBVR)
4.5V to 18V Input, 500mA Synchronous Step Down SWIFT Converter with Advanced Eco-mode, DBV0005A; Manufacturer: Texas Instruments; SymbolCreator: a0411947; CompType: IC; U/M: EA
footprint DBV0005A_N (SOT23, 5-Leads, Body 2.9x1.6mm, Pitch 0.95mm, Lead Span 2.8mm, IPC Medium Density)
footprint DBV0005A_M
footprint DBV0005A_L
pins: 1 EN (in), 2 GND (power), 3 PH (power), 4 VIN (power), 5 VSENSE (in)
2 alternate drawings of the same symbol

## TPS561201DDCR
designator U?
4.5-V to 17-V Input, 2-A Synchronous Step-Down Voltage Regulator, DDC0006A (SOT-23-T-6); Alternate PartNumber: TPS561201DDCT; Manufacturer: Texas Instruments; SymbolCreator: a0411947; CompType: IC; U/M: EA; SizeArea_mm2: 4.8675; SizeAreaWB_mm2: 10.4675; SizeX_mm: 1.65; SizeY_mm: 2.95; SizeZ_mm: 0.87
footprint DDC0006A_N
footprint DDC0006A_M
footprint DDC0006A_L
pins: 1 GND (power), 2 SW (power), 3 VIN (power), 4 VFB (in), 5 EN (in), 6 VBST (power)

## UMK107AB7105KA-T
designator C?, comment ValueDisplayed: 1µF  (hidden comment: UMK107BJ105KA-T)
CAP, CERM,  1UF 50V X5R 0603; Manufacturer: Taiyo Yuden; Polarized: N; CompType: Capacitor; U/M: EA; Cap_F: 0.000001; Tolerance_%: 10; VDC_V: 50; TempCo: X7R; TaMin_C: -55; TaMax_C: 125; Cap_Case: 0603; SizeArea_mm2: 1.28; SizeAreaWB_mm2: 4.68; SizeX_mm: 1.6; SizeY_mm: 0.8; SizeZ_mm: 1; AEC Category: Q200; Green_Lifecycle: Active; Green_REACh: Passed
signal-integrity model Cap
simulation model Cap
footprint 0603
footprint 0603M
footprint 0603L
footprint 0603_HV
footprint 0603S
pins: 1, 2

## UMK316B7225KL-T
designator C?  ValueDisplayed: 2.2µF  (hidden comment: UMK316B7225KL-T)
CAP, CERM, 2.2 µF, 50 V, +/- 10%, X7R, 1206; Manufacturer: Taiyo Yuden; Polarized: N; CompType: Capacitor; Value: 2.2uF; U/M: EA; Cap_F: 0.0000022; Tolerance_%: 10; Value1: Unknown; VDC_V: 50; Value2: 50V; TaMin_C: -55; TaMax_C: 125; Cap_Case: 1206; SizeArea_mm2: 5.12; SizeAreaWB_mm2: 10.92; SizeX_mm: 3.2; SizeY_mm: 1.6; SizeZ_mm: 1.35; AEC Category: Q200
signal-integrity model Cap
simulation model Cap
footprint 1206
footprint 1206M
footprint 1206L
pins: 1, 2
